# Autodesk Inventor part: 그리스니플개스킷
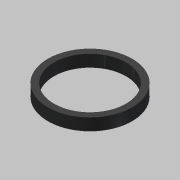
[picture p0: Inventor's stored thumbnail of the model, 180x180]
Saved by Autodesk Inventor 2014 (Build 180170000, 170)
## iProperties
Created: 2019-05
Part Number: 그리스니플개스킷
Material: 고무
Document SubType Name: Modeling
Designer: mduedu
Density: 1 g/cm^3
Appearance: 고무 - 검은색 - 버전 1.1
Author: mduedu
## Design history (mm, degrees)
sketch "스케치1"
  geometry: C1 r 3 at (0, 0); C2 r 3.5 at (0, 0); 1 further point
  constraints: 2 centre point, 2 coincident
  dimensions: "d0" = 6 diameter of C1; "d1" = 7 diameter of C2
extrude "돌출1" new body sketch "스케치1" distance "d2" = 1; taper "d3" = 0 deg
node "솔리드1"
